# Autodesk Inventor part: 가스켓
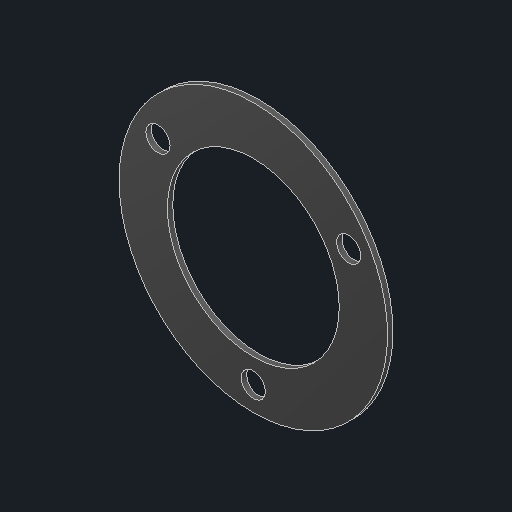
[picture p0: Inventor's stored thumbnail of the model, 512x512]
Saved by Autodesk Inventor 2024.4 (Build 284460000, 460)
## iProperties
Created: 2025-10
Part Number: 가스켓
Material: 스테인리스스틸
Document SubType Name: Modeling
Designer: user
Density: 8 g/cm^3
Appearance: 기본값
Author: jhkim
Sending System: Autodesk Inventor 2026
Preprocessor: ST-DEVELOPER v20.1
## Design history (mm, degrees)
feature "솔리드1"
node "솔리드2"
